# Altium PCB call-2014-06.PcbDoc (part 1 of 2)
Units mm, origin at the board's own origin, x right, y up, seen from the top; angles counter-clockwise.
Board outline 60 x 92 mm, 2 copper layers (Top Layer, Bottom Layer); 65 components, 45 nets, 265 pads, 33 vias.
Unrouted connection lines stored in the file: 4.
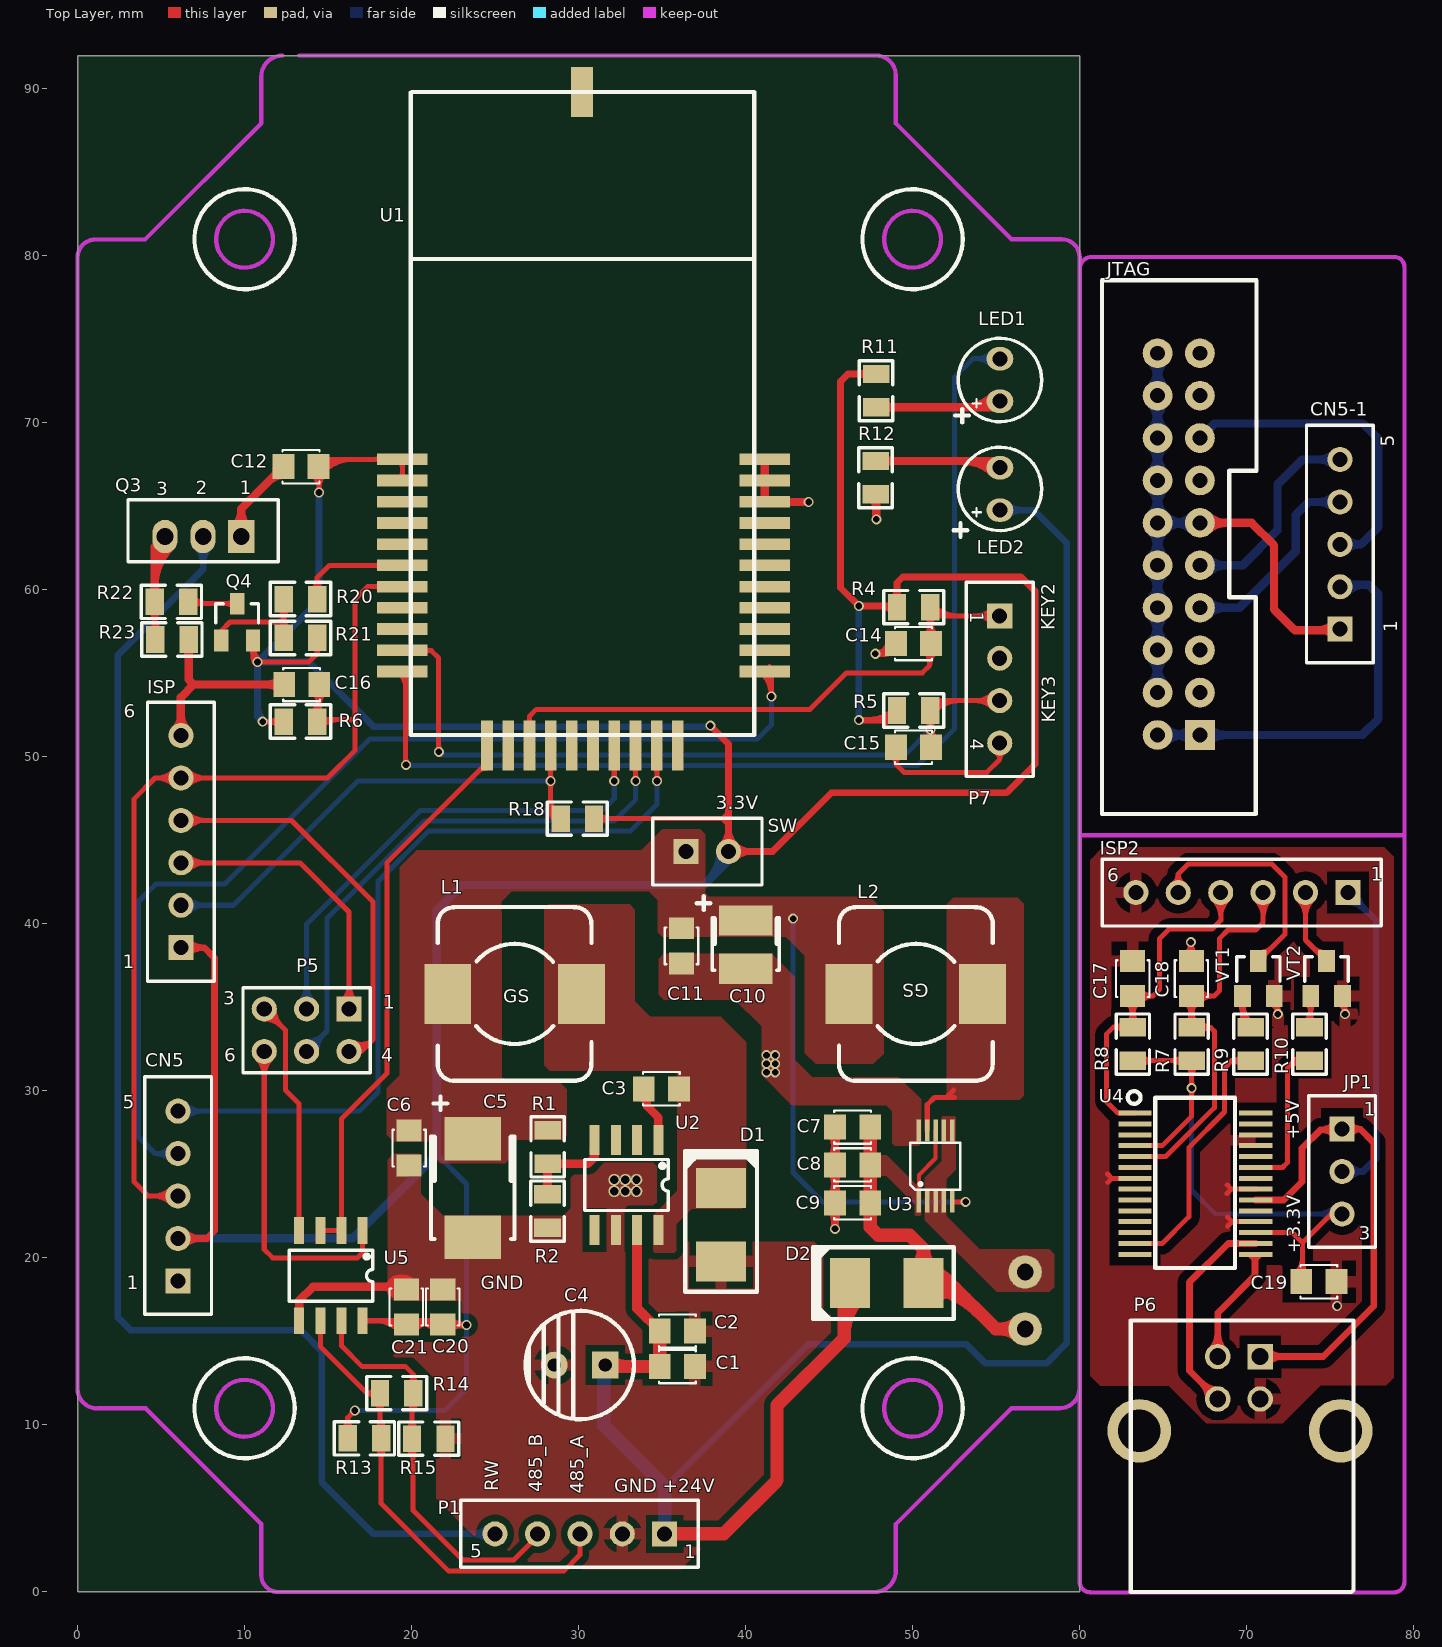
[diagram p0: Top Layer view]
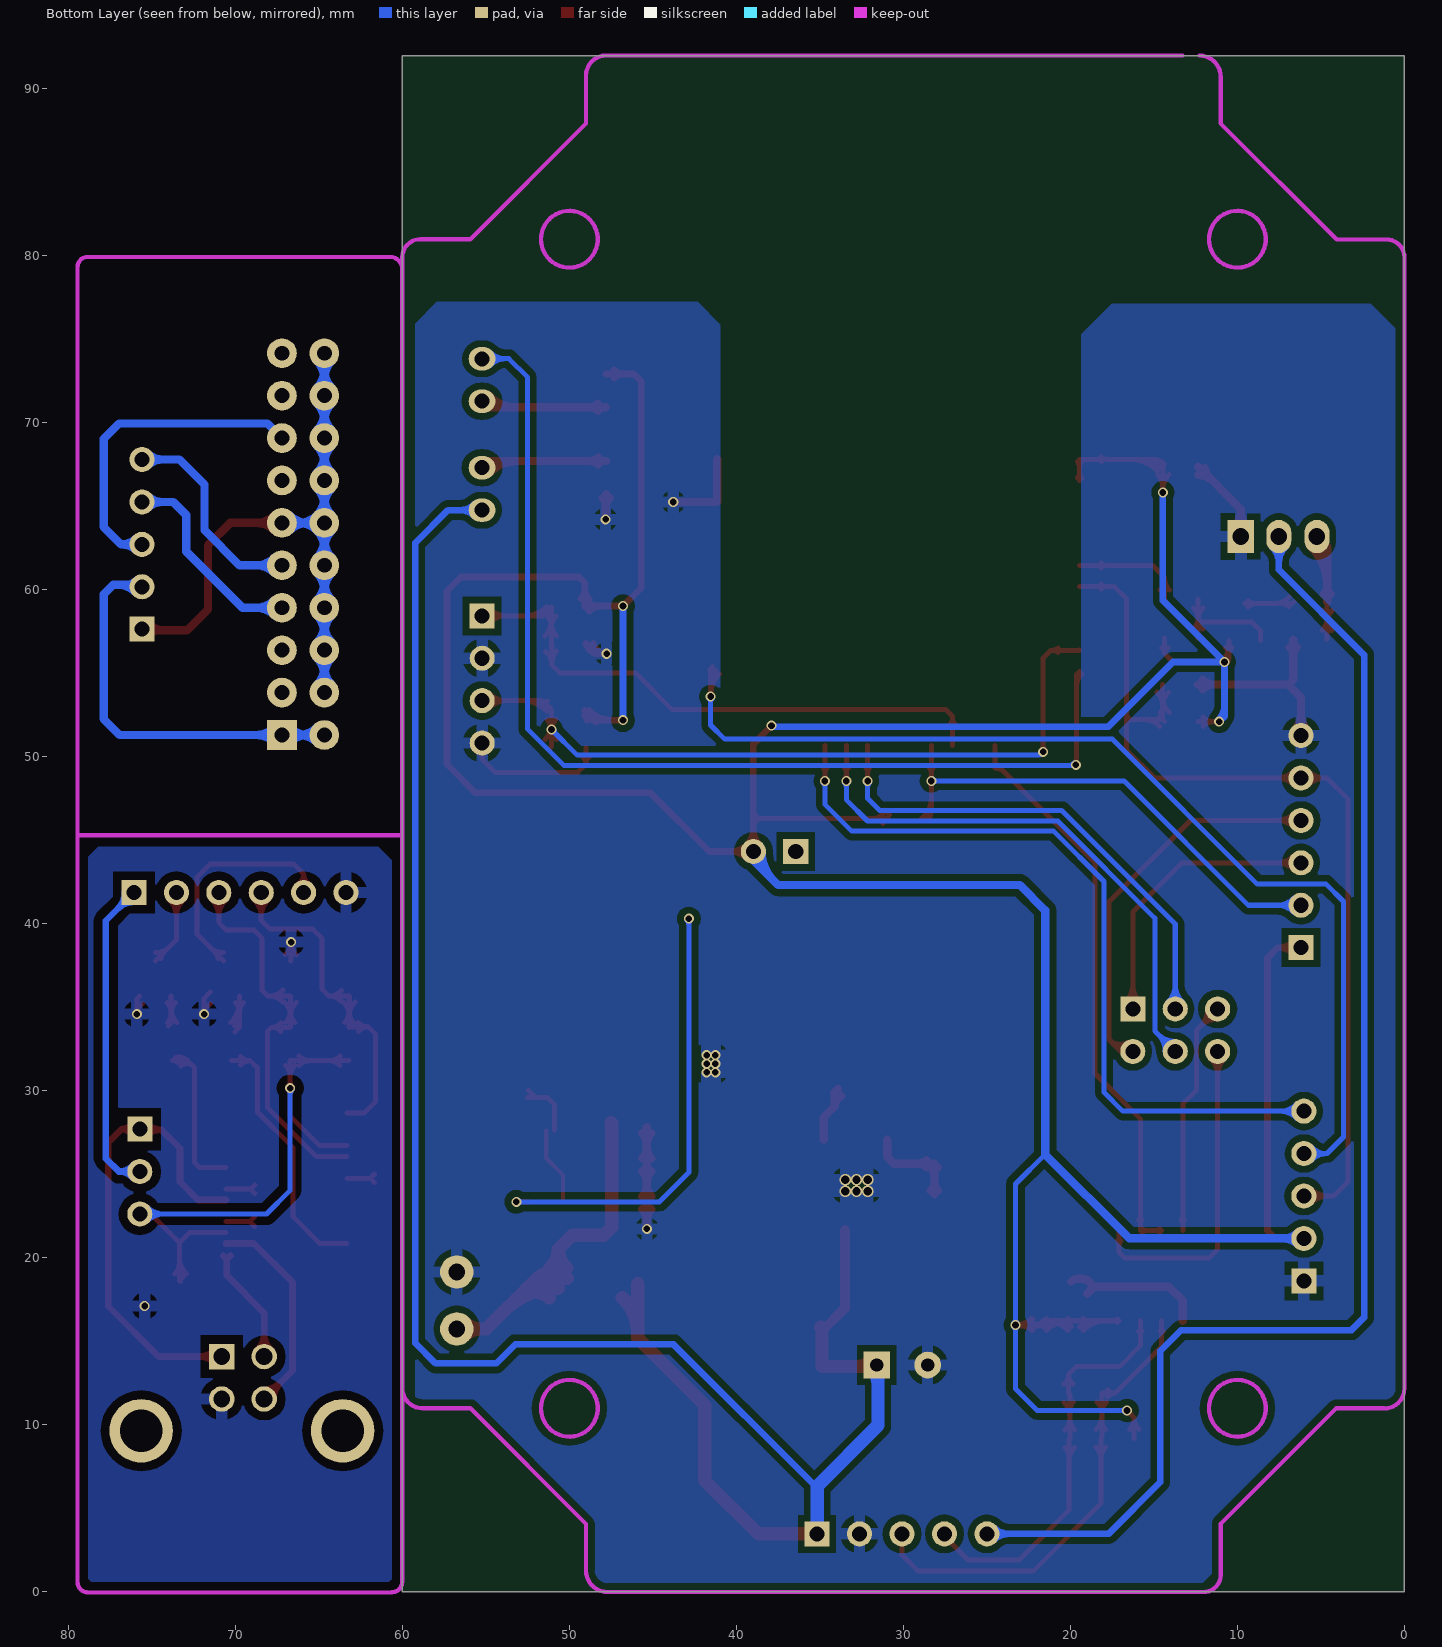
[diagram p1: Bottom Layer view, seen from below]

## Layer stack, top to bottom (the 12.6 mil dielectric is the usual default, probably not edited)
Top Layer: signal copper 0.0356
Dielectric: dielectric 0.32, FR-4, Dk 4.8
Bottom Layer: signal copper 0.0356

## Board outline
0,0 60,0 60,92 0,92

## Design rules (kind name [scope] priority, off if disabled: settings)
Clearance [All] p1: gap=0.2
ComponentClearance [All] p1: gap=0.254 collisioncheckmode=3 verticalgap=0.254
PolygonConnect [All] p1: connectstyle=Relief reliefconductorwidth=0.7 reliefentries=4 polygonreliefangle="90 Angle"
RoutingVias [All] p1: holewidth=0.711 width=1.27 viastyle="Through Hole" minholewidth=0.711 minwidth=1.27 maxholewidth=0.711 maxwidth=1.27
SolderMaskExpansion [All] p1: expansion=0.102
TestPointUsage [All] p1: valid=0 allowmultiple=FALSE
Testpoint [All] p1: side=15 testpointundercomponent=TRUE minsize=1.016 maxsize=2.54 preferedsize=1.524 minholesize=0 maxholesize=1.016 preferedholesize=0.813 testpointgrid=0.025 style=1023 order=0-112345678
Width [All] p1: maxlimit=2 minlimit=0.2 preferedwidth=0.254 toplayer_prefwidth=0.3 bottomlayer_prefwidth=0.3 minimp=50.000000 maximp=50.000000 favimp=50.000000
18 further rules are at their usual default settings.

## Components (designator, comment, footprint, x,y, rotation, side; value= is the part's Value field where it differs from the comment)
C1 "4.7μF/10%/0805" C-0805 37.62,14.4 r180 top
C2 "4.7μF/10%/0805" C-0805 37.62,16.52 r180 top
C3 "0.01μF/10%/0805" C-0805 33.26,29.23 r0 top
C4 "220μF" CZ3.0/6.5 30.07,13.59 r0 top
C5 "476C" C-TAN-D 21.17,28.43 r270 top
C6 "0.1μf/10%/0805" C-0805 20.75,24.88 r90 top
C7 "4.7μF/10%/0805" C-0805 44.71,26.94 r0 top
C8 "4.7μF/10%/0805" C-0805 44.71,24.67 r0 top
C9 "4.7μF/10%/0805" C-0805 44.71,22.4 r0 top
C10 "47uF/20%/10V/B" C-TAN-B 38.015,41.118 r270 top
C11 "0.1μf/10%/0805" C-0805 37.065,36.988 r90 top
C12 "0.1uf/10%/0805" C-0805 11.684,66.481 r0 top
C14 "0.1uf/10%/0805" C-0805 48.36,55.89 r0 top
C15 "0.1uf/10%/0805" C-0805 48.36,49.68 r0 top
C16 "0.1uf/10%/0805" C-0805 11.72,53.436 r0 top
C17 "100pf/10%/0805" C-0805 62.28,38.43 r270 top
C18 "100pf/10%/0805" C-0805 65.797,38.43 r270 top
C19 "0.1μf/10%/0805" C-0805 76.03,19.48 r180 top
C20 "0.1uf/10%/0805" C-0805 20.97,18.76 r270 top
C21 "1uf/10%/0805" C-0805 18.79,18.76 r270 top
CN5 "1*5/排针" PIN-S-2.54-1*5 6.02,18.63 r90 top
CN5-1 "1*5/排针座" PIN-S-2.54-1*5 75.59,57.65 r90 top
D1 "SMB" SMB 40.63,18.48 r90 top
D2 "1N5408/SMB" smb 51.96,20.59 r180 top
ISP "1*6/排针" PIN-S-2.54-1*6 6.19,38.58 r90 top
ISP2 "1*6/排针座" PIN-S-2.54-1*6 76.07,41.88 r180 top locked
JP1 "1*3/排针" PIN-S-2.54-1*3 75.72,27.71 r270 top
JTAG "2*10/排针" IDC-20 67.21,51.29 r90 top
L1 "15μH" GSDS104C2 26.17,35.81 r270 top
L2 "15μH" GSDS104C2 50.196,35.81 r270 top
LED1 "green LED" LED-φ3 55.23,72.57 r90 top
LED2 "VDD33" LED-φ3 55.23,66.05 r90 top
P1 "1*5/2.5" PIN-S-2.54-1*5 35.16,3.48 r180 top locked
P5 "2*3/排针" HDR2X3_CEN 16.26,34.91 r180 top
P6 "Header1*4" USB_B_90D 70.84,14.12 r270 top locked
P7 "1*4/2.54排针" PIN-S-2.54-1*4 55.22,58.45 r270 top (schematic designator P6)
Q3 "D882/TO-126" TO-126 7.52,63.199 r180 top
Q4 "MMBT3906LT1G/SOT-23" SOT-23 8.23,56.34 r0 top
R1 "10K" R-0805 29.05,25.15 r90 top
R2 "5.9K/1%/0805" R-0805 27.24,24.31 r270 top
R4 "10K/5%/0805" R-0805 51.57,59.87 r180 top
R5 "10K/5%/0805" R-0805 51.57,53.68 r180 top
R6 "10K/5%/0805" R-0805 14.851,53.016 r180 top
R7 "3.3K/5%/0805" R-0805 65.817,34.31 r270 top
R8 "3.3K/5%/0805" R-0805 62.29,34.31 r270 top
R9 "1K/5%/0805" R-0805 69.343,34.31 r270 top
R10 "1K/5%/0805" R-0805 72.87,34.31 r270 top
R11 "3.3K/5%/0805" R-0805 46.92,73.43 r270 top
R12 "1.5K/5%/0805" R-0805 48.69,65.22 r90 top
R13 "3.3K/5%/0805" R-0805 18.68,10.1 r180 top
R14 "120ohm" R-0805 20.61,12.8 r180 top
R15 "3.3K/5%/0805" R-0805 22.53,10.08 r180 top
R18 "10K/5%/0805" R-0805 28.425,45.404 r0 top
R20 "1K/5%/0805" R-0805 11.851,58.55 r0 top
R21 "10K/5%/0805" R-0805 11.851,56.23 r0 top
R22 "1K/5%/0805" R-0805 4.12,58.39 r0 top
R23 "10K/5%/0805" R-0805 7.15,57.93 r180 top
SW "SW-1" PIN-S-2.54-1*2 36.444,44.335 r0 top
U1 "STM32W_1" STM32W108-3 40.52,51.31 r90 top locked
U2 "TPS5430" SO-G8#1 32.86,24.37 r180 top locked
U3 "TPS62056" MSOP-10 50.38,23.46 r0 top locked
U4 "FT232R" SSOP-28 63.32,28.67 r0 top
U5 "MAX3485CSA" SO-G8#2 15.16,18.94 r180 top
VT1 "2N3904" SOT23-3 69.753,35.68 r0 top
VT2 "2N3904" SOT23-3 73.84,35.68 r0 top

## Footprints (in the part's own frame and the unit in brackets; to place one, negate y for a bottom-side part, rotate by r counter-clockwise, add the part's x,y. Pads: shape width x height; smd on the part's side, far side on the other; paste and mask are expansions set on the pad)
C-0805 [mm]
  rect 1.3x1.5 smd: 1(0.65,0.9) 2(2.75,0.9)
  silkscreen extent 0.6,-0.1 2.8,1.9
C-TAN-B [mm]
  rect 1.8x3.2 smd: 1(0.9,2) 2(3.8,2)
  silkscreen extent 0.75,0 3.9,4
C-TAN-D [mm]
  rect 2.6x3.4 smd: 1(1.3,2.5) 2(7.2,2.5)
  silkscreen extent 1.15,0 7.3,5
CZ3.0/6.5 [mm]
  rect 1.6x1.6 hole 0.8: 1(1.524,0)
  round 1.6 hole 0.8: 2(-1.524,0)
  silkscreen extent -3.25,-3.25 3.25,3.25
GSDS104C2 [mm]
  rect 3.6x2.8 smd: 1(0,4) 2(0,-4)
  silkscreen extent -5.2,-4.6 5.21,4.6
HDR2X3_CEN [mm] "Connector; Header; 3x2 Position"
  rect 1.5x1.5 hole 0.9: 1(0,0)
  round 1.5 hole 0.9: 2(2.54,0) 3(5.08,0) 4(0,2.54) 5(2.54,2.54) 6(5.08,2.54)
  silkscreen extent -1.27,-1.27 6.35,3.81
IDC-20 [mil]
  rect 70x70 hole 35: 1(1,0)
  round 70 hole 35: 2(1,100) 3(101,0) 4(101,100) 5(201,0) 6(201,100) 7(301,0) 8(301,100) 9(401,0) 10(401,100) 11(501,0) 12(501,100) 13(601,0) 14(601,100) 15(701,0) 16(701,100) 17(801,0) 18(801,100) 19(901,0) 20(901,100)
  silkscreen extent -185,-133 1073,231
LED-φ3 [mm]
  oval 1.4x1.6 hole 0.9: 1(-1.27,0) 2(1.27,0)
  silkscreen extent -2.5,-2.5 2.5,2.5
MSOP-10 [mm]
  rect 0.27x1.3 smd mask+0.05: 1(0,-0.1) 2(0.5,-0.1) 3(1,-0.1) 4(1.5,-0.1) 5(2,-0.1) 6(2,4.175) 7(1.5,4.175) 8(1,4.175) 9(0.5,4.175) 10(0,4.175)
  silkscreen extent -0.51,0.64 2.46,3.43
PIN-S-2.54-1*2 [mm]
  rect 1.5x1.5 hole 0.9: 1(0,0)
  round 1.5 hole 0.9: 2(2.54,0)
  silkscreen extent -2,-2 4.54,2
PIN-S-2.54-1*3 [mm]
  rect 1.5x1.5 hole 0.9: 1(0,0)
  round 1.5 hole 0.9: 2(2.54,0) 3(5.08,0)
  silkscreen extent -2,-2 7.08,2
PIN-S-2.54-1*4 [mm]
  rect 1.5x1.5 hole 0.9: 1(0,0)
  round 1.5 hole 0.9: 2(2.54,0) 3(5.08,0) 4(7.62,0)
  silkscreen extent -2,-2 9.62,2
PIN-S-2.54-1*5 [mm]
  rect 1.5x1.5 hole 0.9: 1(0,0)
  round 1.5 hole 0.9: 2(2.54,0) 3(5.08,0) 4(7.62,0) 5(10.16,0)
  silkscreen extent -2,-2 12.22,2
PIN-S-2.54-1*6 [mm]
  rect 1.5x1.5 hole 0.9: 1(0,0)
  round 1.5 hole 0.9: 2(2.54,0) 3(5.08,0) 4(7.62,0) 5(10.16,0) 6(12.7,0)
  silkscreen extent -2,-2 14.7,2
R-0805 [mm]
  rect 1.1x1.6 smd: 1(0.5,0.9) 2(2.5,0.9)
  silkscreen extent -0.3,-0.1 3.3,1.9
SMB [mm]
  rect 2.4x3 smd: 1(1.3,2.1) 2(5.7,2.1)
  silkscreen extent -0.51,-0.05 7.92,4.24
smb [mm]
  rect 2.4x3 smd: 1(1.3,2.1) 2(5.7,2.1)
  silkscreen extent -0.51,-0.05 7.92,4.24
SO-G8#1 [mm]
  rect 0.6x1.8 smd: 1(-1.916,-2.7) 2(-0.646,-2.7) 3(0.624,-2.7) 4(1.894,-2.7) 5(1.894,2.7) 6(0.624,2.7) 7(-0.646,2.7) 8(-1.916,2.7)
  silkscreen extent -2.51,-1.52 2.49,1.52
SO-G8#2 [mm]
  rect 0.6x1.6 smd: 1(-1.916,-2.7) 2(-0.646,-2.7) 3(0.624,-2.7) 4(1.894,-2.7) 5(1.894,2.7) 6(0.624,2.7) 7(-0.646,2.7) 8(-1.916,2.7)
  silkscreen extent -2.51,-1.52 2.49,1.52
SOT23-3 [mm]
  rect 1x1.3 smd: 1(0,0) 2(1.9,0) 3(0.95,2.1)
  silkscreen extent -0.35,0.87 2.25,2.35
SOT-23 [mm]
  rect 0.85x1.3 smd: 1(0.381,0.635) 2(2.281,0.635) 3(1.331,2.835)
  silkscreen extent 0.06,1.68 2.61,2.83
SSOP-28 [mm]
  rect 2x0.3 smd: 1(0,0) 2(0,-0.65) 3(0,-1.3) 4(0,-1.95) 5(0,-2.6) 6(0,-3.25) 7(0,-3.9) 8(0,-4.55) 9(0,-5.2) 10(0,-5.85) 11(0,-6.5) 12(0,-7.15) 13(0,-7.8) 14(0,-8.45) 15(7.239,-8.45) 16(7.239,-7.8) 17(7.239,-7.15) 18(7.239,-6.5) 19(7.239,-5.85) 20(7.239,-5.2) 21(7.239,-4.55) 22(7.239,-3.9) 23(7.239,-3.25) 24(7.239,-2.6) 25(7.239,-1.95) 26(7.239,-1.3) 27(7.239,-0.65) 28(7.239,0)
  silkscreen extent -0.43,-9.27 5.99,1.32
STM32W108-3 [mm]
  rect 0.7x3 smd: 1(16.51,21.074) 2(15.24,21.074) 3(13.97,21.074) 4(12.7,21.074) 5(11.43,21.074) 6(10.16,21.074) 7(8.89,21.074) 8(7.62,21.074) 9(6.35,21.074) 10(5.08,21.074) 11(3.81,21.074) 22(3.81,-0.627) 23(5.08,-0.627) 24(6.35,-0.627) 25(7.62,-0.627) 26(8.89,-0.627) 27(10.16,-0.627) 28(11.43,-0.627) 29(12.7,-0.627) 30(13.97,-0.627) 31(15.24,-0.627) 32(16.51,-0.627)
  rect 3x0.7 smd: 12(-0.627,16.002) 13(-0.627,14.732) 14(-0.627,13.462) 15(-0.627,12.192) 16(-0.627,10.922) 17(-0.627,9.652) 18(-0.627,8.382) 19(-0.627,7.112) 20(-0.627,5.842) 21(-0.627,4.572)
  rect 3x1.3 smd: ""(38.5,10.314)
  silkscreen extent 0,0 38.5,20.57
TO-126 [mm]
  rect 1.6x2 hole 1: 1(-2.28,0)
  oval 1.5x2 hole 1: 2(0,0) 3(2.28,0)
  silkscreen extent -4.5,-2.2 4.5,1.5
USB_B_90D [mil] "180度 横插 方口USB母座"
  rect 60.06x60.06 hole 40: 1(1,-1)
  round 60.06 hole 40: 2(1,-101) 3(101,-101) 4(101,-1)
  round 150 hole 100: 5(176,-286) 6(176,189)
  silkscreen extent -84,-306 556,219

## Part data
C1 C2 C3 C6 C7 C8 C9 C11 C12 C14 C15 C16 C17 C18 C19 C20 C21: library part Cap, "Capacitor"
C4 C5: library part "Cap Pol1", "Polarized Capacitor (Radial)"
C10: library part ASC-0013BA
CN5 CN5-1: library part Header1*5
D1 D2: library part "Diode 1N5408", "3 Amp Medium Power Silicon Rectifier Diode"
ISP ISP2: library part Header1*6
JP1: library part Header1*3
JTAG: library part Header2*10
L1 L2: library part Inductor, "Inductor"
LED1: library part LED
LED2: library part LED3, "Typical BLUE SiC LED"
P1 P6 P7: library part "Header 4", "Header, 4-Pin"
P5: library part "Header 3X2A", "Header, 3-Pin, Dual row"
Q3: library part NPN-1E2C3B
Q4: library part ASQ-0009BA
R1 R2 R4 R5 R6 R12 R18: library part Res2, "Resistor"
R7 R8: library part RES_1
R9 R10 R11 R13 R14 R15 R20 R21 R22 R23: library part RES, "R"
U1: library part STM32W108-3
U5: library part MAX485CSA, "Low-Power, Slew-Rate-Limited RS-485/RS-422 Transceiver"
VT1 VT2: library part NPN, "NPN Transistor"

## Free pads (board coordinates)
  round 0.7 hole 0.5: 0(32.137,23.996) 0(32.137,24.683) 1(32.804,23.996) 1(32.804,24.683) 2(33.472,23.996) 2(33.472,24.683)
  round 2 hole 1: 0(56.74,15.75) 1(56.74,19.16)

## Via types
v1: diameter 0.6, hole 0.4, Top Layer to Bottom Layer, 33 vias

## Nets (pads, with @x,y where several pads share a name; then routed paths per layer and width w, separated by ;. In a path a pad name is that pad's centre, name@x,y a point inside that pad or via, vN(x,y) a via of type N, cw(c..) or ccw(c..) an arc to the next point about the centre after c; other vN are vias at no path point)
485_A: P1.3 R13.1 R14.2 U5.6 | length 34.3
  Top Layer w0.3: U5.6@14.43,15.634 cw(c14.174,15.378) 14.536,15.378 cw(c14.898,15.378) U5.6@14.642,15.634 ; U5.6@14.536,16.24 14.536,14.694 17.33,11.9 ; R14.2@17.785,11.667 ccw(c17.33,11.34) 17.33,11.9 ; R14.2@17.785,12.133 cw(c17.33,12.46) 17.33,11.9 ; R14.2@17.827,11.367 cw(c17.144,10.684) 18.11,10.684 cw(c19.076,10.684) R14.2@18.393,11.367 ; R13.1@17.897,8.667 cw(c17.214,7.984) 18.18,7.984 cw(c19.146,7.984) R13.1@18.463,8.667 ; R13.1@17.897,9.733 ccw(c17.383,10.247) 18.11,10.247 ; 18.11,10.585 ccw(c19.315,10.585) R13.1@18.463,9.733 ; P1.3@30.08,3.48 30.08,2.21 29.116,1.246 22.23,1.246 18.18,5.296 R13.1@18.18,9.2 18.11,9.27 R14.2@18.11,11.9 17.33,11.9
485_B: P1.4 R14.1 R15.2 U5.7 | length 30.6
  Top Layer w0.3: U5.7@15.7,15.634 cw(c15.444,15.378) 15.806,15.378 cw(c16.168,15.378) U5.7@15.912,15.634 ; U5.7@15.806,16.24 15.806,14.734 17.05,13.49 19.65,13.49 20.11,13.03 ; R15.2@19.747,8.647 cw(c18.919,7.819) 20.09,7.819 ; R15.2@19.747,9.713 ccw(c19.064,10.396) 20.03,10.396 ccw(c20.996,10.396) R15.2@20.313,9.713 ; R14.1@19.827,11.367 cw(c19.337,10.877) 20.03,10.877 ; R14.1@19.847,12.451 ccw(c19.342,13.03) 20.11,13.03 ; 20.03,10.491 cw(c21.269,10.491) R14.1@20.393,11.367 ; 20.09,8.109 cw(c20.851,8.109) R15.2@20.313,8.647 ; R14.1@20.373,12.451 cw(c20.878,13.03) 20.11,13.03 ; P1.4@27.54,3.48 27.54,3.328 26.125,1.913 23.07,1.913 20.09,4.893 20.09,9.12 R15.2@20.03,9.18 20.03,11.82 R14.1@20.11,11.9 20.11,13.03
+VBRD: CN5-1.2 JTAG.1 JTAG.2 | length 32.8
  Bottom Layer w0.5: JTAG.2@64.67,51.315 76.925,51.315 77.89,52.28 77.89,59.74 77.31,60.32 75.72,60.32 CN5-1.2@75.59,60.19 ; JTAG.2@65.122,50.864 cw(c66.213,49.773) 66.213,51.315 cw(c66.213,52.858) JTAG.2@65.122,51.767 ; JTAG.1@66.758,50.864 ccw(c65.667,49.773) 65.667,51.315 ccw(c65.667,52.858) JTAG.1@66.758,51.767 ; JTAG.1@67.662,50.864 cw(c68.753,49.773) 68.753,51.315 cw(c68.753,52.858) JTAG.1@67.662,51.767 ; CN5-1.2@75.944,59.836 cw(c77.111,58.669) 77.111,60.32 ; CN5-1.2@75.944,60.544 ccw(c76.483,61.083) 76.483,60.32
/RESET: C16.2 CN5-1.3 CN5.3 ISP2.5 ISP.5 JTAG.15 R6.1 U1.7 VT1.3 | length 107.7
  Top Layer w0.3: CN5.3@5.596,23.286 ccw(c4.571,22.261) 4.571,23.71 ccw(c4.571,25.159) CN5.3@5.596,24.134 ; ISP.5@5.766,48.316 ccw(c4.741,47.291) 4.741,48.74 ccw(c4.741,50.189) ISP.5@5.766,49.164 ; CN5.3@6.02,23.71 4.23,23.71 3.39,24.55 3.39,47.49 4.64,48.74 14.967,48.74 16.628,50.401 16.628,59.461 17.367,60.2 U1.7@19.446,60.2 ; ISP.5@6.614,48.316 cw(c7.639,47.291) 7.639,48.74 cw(c7.639,50.189) ISP.5@6.614,49.164 ; R6.1@14.068,52.649 ccw(c13.098,53.619) C16.2@14.47,53.619 ; C16.2@14.116,53.882 cw(c13.263,53.029) 14.47,53.029 cw(c15.677,53.029) C16.2@14.824,53.882 ; R6.1@14.351,52.116 R6.1@14.47,52.235 ; 14.47,53.044 ccw(c15.029,53.044) R6.1@14.634,52.649 ; C16.2@14.47,54.336 R6.1@14.47,52.235 ; R6.1@14.634,51.833 cw(c15.604,50.863) 15.604,52.235 ; R6.1@14.634,52.399 ccw(c15.029,52.794) 15.029,52.235 ; 16.628,52.019 16.412,52.235 ; 16.628,52.451 16.412,52.235 ; U1.7@18.155,60.059 ccw(c17.813,59.717) 17.813,60.2 ccw(c17.813,60.683) U1.7@18.155,60.341 ; ISP2.5@65.581,42.382 ccw(c65.183,42.99) 65.91,42.99 ; ISP2.5@65.91,41.88 65.91,42.99 ; ISP2.5@66.239,42.382 cw(c66.637,42.99) 65.91,42.99 ; VT1.3@70.703,37.78 72.29,39.367 72.29,42.81 71.51,43.59 66.51,43.59 65.91,42.99 ; VT1.3@70.703,38.28 ccw(c70.703,39.487) 71.556,38.634 ; VT1.3@71.053,37.93 cw(c71.536,37.93) VT1.3@71.194,38.271 ; R6.1@14.47,52.235 16.412,52.235
  Bottom Layer w0.5: JTAG.15@67.21,69.095 68.085,69.97 76.96,69.97 77.89,69.04 77.89,63.78 76.84,62.73 CN5-1.3@75.59,62.73 ; CN5-1.3@75.944,62.376 cw(c76.797,61.523) 76.797,62.73 cw(c76.797,63.937) CN5-1.3@75.944,63.084
BOOT: ISP2.2 ISP.2 R18.1 U1.15 VT2.3 | length 44.7
  Top Layer w0.3: U1.15@28.187,49.392 cw(c27.845,49.05) 28.328,49.05 cw(c28.811,49.05) U1.15@28.469,49.392 ; v1@28.222,48.453 cw(c27.966,48.197) 28.328,48.197 cw(c28.69,48.197) v1@28.434,48.453 ; v1@28.222,48.665 ccw(c27.966,48.921) 28.328,48.921 ccw(c28.69,48.921) v1@28.434,48.665 ; 28.328,46.788 ccw(c29.159,46.788) R18.1@28.571,46.2 ; 28.328,47.512 ccw(c29.883,47.512) R18.1@28.784,46.413 ; U1.15@28.328,50.683 28.328,46.901 R18.1@28.925,46.304 ; ISP2.2@73.106,41.456 cw(c72.081,40.431) 73.53,40.431 cw(c74.979,40.431) ISP2.2@73.954,41.456 ; ISP2.2@73.53,41.88 73.53,39.04 VT2.3@74.79,37.78 ; 73.936,38.634 ccw(c74.79,39.487) VT2.3@74.79,38.28 ; VT2.3@74.299,38.271 cw(c73.957,37.93) VT2.3@74.44,37.93
  Bottom Layer w0.3: ISP.2@6.19,41.12 9.342,41.12 16.781,48.559 v1(28.328,48.559) ; ISP.2@6.614,40.696 cw(c7.639,39.671) 7.639,41.12 cw(c7.639,42.569) ISP.2@6.614,41.544 ; v1@28.222,48.453 ccw(c27.966,48.197) 27.966,48.559 ccw(c27.966,48.921) v1@28.222,48.665
CBUS0: R10.2 U4.23 | length 13.5
  Top Layer w0.3: U4.23@70.559,25.42 72.15,25.42 72.44,25.71 72.44,31.4 72.85,31.81 ; 72.476,31.436 cw(c73.228,30.684) R10.2@73.495,31.713 ; 72.515,31.475 cw(c72.904,31.086) R10.2@73.261,31.505 ; 72.745,31.705 cw(c73.116,31.334) R10.2@73.455,31.734 ; 72.847,31.807 cw(c73.381,31.273) R10.2@73.57,32.004 ; R10.2@73.168,31.62 ccw(c72.85,31.449) 72.85,31.81 ; R10.2@73.168,32 cw(c72.85,32.171) 72.85,31.81 ; R10.2@73.77,31.81 72.85,31.81
CBUS2: R9.2 U4.13 | length 16.7
  Top Layer w0.3: U4.13@63.32,20.87 64.95,20.87 66.54,22.46 66.54,26.606 68.678,28.744 68.678,31.378 69.11,31.81 ; R9.2@69.693,31.546 ccw(c69.11,31.035) 69.11,31.81 ; R9.2@69.693,32.074 cw(c69.11,32.585) 69.11,31.81 ; R9.2@70.243,31.81 69.11,31.81
D+: P6.2 U4.15 | length 9.5
  Top Layer w0.4: P6.2@67.877,14.492 ccw(c66.916,15.453) 68.275,15.453 ccw(c69.633,15.453) P6.2@68.672,14.492 ; P6.2@68.275,14.095 68.275,16.715 70.51,18.95 70.51,19.92 ; U4.15@70.29,20.14 70.51,19.92 ; U4.15@70.73,20.14 70.51,19.92
D-: P6.3 U4.16 | length 14.8
  Top Layer w0.4: P6.3@67.712,11.555 ccw(c66.353,11.555) 67.314,12.515 ccw(c68.275,13.476) P6.3@68.275,12.117 ; P6.3@68.275,11.555 66.58,13.249 66.58,18.55 68.9,20.87 U4.16@70.559,20.87
GND: C1.1 C2.1 C4.2 C5.2 C6.1 C7.1 C8.1 C9.1 C10.2 C11.1 C12.1 C14.1 C15.1 C16.1 C17.1 C18.1 C19.1 C20.1 C21.1 CN5.1 D1.1 ISP2.6 ISP.6 P1.2 P6.4 P7.2 P7.4 pad.0@32.137,23.996 pad.0@32.137,24.683 pad.1 pad.2 Q3.1 R2.2 R12.1 R15.1 R23.1 U1.30 U1.31 U1.32 U2.6 U3.2 U3.3 U3.4 U3.6 U3.7 U3.10 U4.7 U4.18 U4.21 U4.25 U4.26 U5.5 VT1.2 VT2.2 | length 85.6
  Top Layer w0.3: C15.1@48.74,50.059 cw(c48.421,49.564) 49.01,49.564 ; C15.1@49.01,50.58 49.01,49.564 ; C15.1@49.28,50.059 ccw(c49.599,49.564) 49.01,49.564 ; P7.4@54.947,50.296 cw(c54.72,49.85) 55.22,49.85 ; P7.4@55.22,50.83 55.22,49.85 ; P7.4@55.493,50.296 ccw(c55.72,49.85) 55.22,49.85 ; 61.67,24.51 61.93,24.77 ; 61.67,25.03 61.93,24.77 ; U4.7@63.32,24.77 61.93,24.77 ; C18.1@66.344,38.134 ccw(c65.58,38.897) v1@66.66,38.897 ; v1@66.554,38.804 cw(c66.298,38.548) 66.66,38.548 cw(c67.022,38.548) v1@66.766,38.804 ; C18.1@66.697,37.78 66.66,37.817 v1(66.66,38.91) ccw(c67.617,38.91) C18.1@67.013,38.168 ; 68.83,23.86 69.09,24.12 ; 68.83,24.38 69.09,24.12 ; 68.85,21.88 69.14,22.17 ; 68.85,22.46 69.14,22.17 ; U4.18@70.559,22.17 69.14,22.17 ; U4.21@70.559,24.12 69.09,24.12 ; VT1.2@71.485,35.223 cw(c71.132,34.575) v1@71.87,34.575 ; VT1.2@71.5,35.92 71.87,35.55 v1(71.87,34.6) ; v1@71.764,34.706 ccw(c71.508,34.962) 71.87,34.962 ccw(c72.232,34.962) v1@71.976,34.706 ; VT2.2@75.548,35.237 cw(c75.122,34.586) v1@75.9,34.586 ; VT2.2@75.74,35.68 75.9,35.52 v1(75.9,34.6) ; v1@75.794,34.706 ccw(c75.538,34.962) 75.9,34.962 ccw(c76.262,34.962) v1@76.006,34.706 ; 49.01,49.564 49.492,49.082 54.452,49.082 55.22,49.85
  Top Layer w0.4: 48.286,56.179 ccw(c48.286,56.876) C14.1@48.962,56.702 ; C14.1@48.574,56.802 cw(c47.77,57.009) v1(47.77,56.179) 48.399,56.179 C14.1@49.01,56.79
  Top Layer w0.5: ISP.6@5.836,51.634 ccw(c4.983,52.487) 6.19,52.487 ccw(c7.397,52.487) ISP.6@6.544,51.634 ; ISP.6@6.19,51.28 6.19,53.571 6.955,54.336 ; R23.1@6.438,56.568 cw(c5.926,56.056) 6.65,56.056 cw(c7.374,56.056) R23.1@6.862,56.568 ; R23.1@6.65,57.03 6.65,54.641 6.955,54.336 ; Q3.1@9.411,63.788 ccw(c8.472,64.727) 9.8,64.727 ccw(c11.128,64.727) Q3.1@10.189,63.788 ; Q3.1@9.8,63.199 9.8,64.847 C12.1@12.334,67.381 ; 11.48,66.527 cw(c12.334,65.674) C12.1@12.334,66.881 ; C12.1@11.722,66.769 ccw(c11.21,67.281) C12.1@11.934,67.281 ; C16.1@12.087,54.053 ccw(c11.404,53.37) 11.404,54.336 ccw(c11.404,55.302) C16.1@12.087,54.619 ; C16.1@12.37,54.336 6.955,54.336 ; U5.5@13.266,16.24 13.266,17.446 14.094,18.274 18.57,18.274 C21.1@18.989,18.693 ; 18.588,18.275 C21.1@19.007,17.856 ; 18.802,18.506 cw(c19.425,17.884) C21.1@19.945,18.594 ; U1.32@41.147,67.833 U1.30@41.147,65.28 41.161,65.266 v1(43.779,65.266) ; C9.1@45.077,22.917 cw(c44.394,22.234) 45.36,22.234 cw(c46.326,22.234) C9.1@45.643,22.917 ; C9.1@45.077,23.683 ccw(c44.394,24.366) 45.36,24.366 ccw(c46.326,24.366) C9.1@45.643,23.683 ; C8.1@45.077,25.187 cw(c44.394,24.504) 45.36,24.504 cw(c46.326,24.504) C8.1@45.643,25.187 ; C8.1@45.077,25.953 ccw(c44.394,26.636) 45.36,26.636 ccw(c46.326,26.636) C8.1@45.643,25.953 ; C7.1@45.077,27.457 cw(c44.394,26.774) 45.36,26.774 cw(c46.326,26.774) C7.1@45.643,27.457 ; v1(45.36,21.742) C7.1@45.36,27.84 ; R12.1@47.578,65.508 cw(c46.976,64.906) 47.827,64.906 ; R12.1@47.79,65.72 47.827,65.683 v1(47.827,64.227) ; 47.827,65.085 cw(c48.425,65.085) R12.1@48.002,65.508
  other v1: 75.43,17.12 41.259,31.118 41.775,31.118 41.259,31.629 41.775,31.629 41.259,32.14 41.775,32.14
GND1: CN5-1.1 JTAG.4 JTAG.6 JTAG.8 JTAG.10 JTAG.11 JTAG.12 JTAG.14 JTAG.16 JTAG.18 JTAG.20 | length 84
  Top Layer w0.5: JTAG.11@67.21,64.015 70.305,64.015 71.64,62.68 71.64,58.84 72.9,57.58 75.52,57.58 CN5-1.1@75.59,57.65 ; JTAG.11@67.662,63.564 cw(c68.753,62.473) 68.753,64.015 cw(c68.753,65.558) JTAG.11@67.662,64.467 ; 74.214,57.58 ccw(c74.214,59.026) CN5-1.1@75.236,58.004 ; 74.552,57.58 cw(c74.552,56.612) CN5-1.1@75.236,57.296
  Bottom Layer w0.5: JTAG.4@64.218,54.307 ccw(c63.127,55.398) 64.67,55.398 ccw(c66.213,55.398) JTAG.4@65.122,54.307 ; JTAG.6@64.218,55.944 cw(c63.127,54.853) 64.67,54.853 cw(c66.213,54.853) JTAG.6@65.122,55.944 ; JTAG.6@64.218,56.847 ccw(c63.127,57.938) 64.67,57.938 ccw(c66.213,57.938) JTAG.6@65.122,56.847 ; JTAG.8@64.218,58.484 cw(c63.127,57.393) 64.67,57.393 cw(c66.213,57.393) JTAG.8@65.122,58.484 ; JTAG.8@64.218,59.387 ccw(c63.127,60.478) 64.67,60.478 ccw(c66.213,60.478) JTAG.8@65.122,59.387 ; JTAG.10@64.218,61.024 cw(c63.127,59.933) 64.67,59.933 cw(c66.213,59.933) JTAG.10@65.122,61.024 ; JTAG.10@64.218,61.927 ccw(c63.127,63.018) 64.67,63.018 ccw(c66.213,63.018) JTAG.10@65.122,61.927 ; JTAG.12@64.218,63.564 cw(c63.127,62.473) 64.67,62.473 cw(c66.213,62.473) 65.122,63.564 cw(c66.213,62.473) 66.213,64.015 cw(c66.213,65.558) 65.122,64.467 cw(c66.213,65.558) 64.67,65.558 cw(c63.127,65.558) JTAG.12@64.218,64.467 ; JTAG.14@64.218,66.104 cw(c63.127,65.013) 64.67,65.013 cw(c66.213,65.013) JTAG.14@65.122,66.104 ; JTAG.14@64.218,67.007 ccw(c63.127,68.098) 64.67,68.098 ccw(c66.213,68.098) JTAG.14@65.122,67.007 ; JTAG.16@64.218,68.644 cw(c63.127,67.553) 64.67,67.553 cw(c66.213,67.553) JTAG.16@65.122,68.644 ; JTAG.16@64.218,69.547 ccw(c63.127,70.638) 64.67,70.638 ccw(c66.213,70.638) JTAG.16@65.122,69.547 ; JTAG.18@64.218,71.184 cw(c63.127,70.093) 64.67,70.093 cw(c66.213,70.093) JTAG.18@65.122,71.184 ; JTAG.18@64.218,72.087 ccw(c63.127,73.178) 64.67,73.178 ccw(c66.213,73.178) JTAG.18@65.122,72.087 ; JTAG.20@64.218,73.724 cw(c63.127,72.633) 64.67,72.633 cw(c66.213,72.633) JTAG.20@65.122,73.724 ; JTAG.4@64.67,53.855 64.67,63.89 64.795,64.015 JTAG.11@67.21,64.015 ; JTAG.12@64.67,64.015 JTAG.20@64.67,74.175 ; JTAG.11@66.758,63.564 ccw(c65.667,62.473) 65.667,64.015 ccw(c65.667,65.558) JTAG.11@66.758,64.467
JNTRST: JTAG.3
JTCK: CN5-1.5 CN5.5 JTAG.9 U1.20 | length 68.3
  Top Layer w0.3: U1.20@34.537,49.392 cw(c34.144,48.999) 34.699,48.999 ; v1@34.593,48.665 ccw(c34.337,48.921) 34.699,48.921 ccw(c35.061,48.921) v1@34.805,48.665 ; U1.20@34.678,50.683 34.699,50.662 v1(34.699,48.559) ; 34.699,49.101 cw(c35.11,49.101) U1.20@34.819,49.392
  Bottom Layer w0.3: CN5.5@6.02,28.79 16.862,28.79 17.987,29.915 17.987,42.541 21.003,45.557 33.089,45.557 34.699,47.167 v1(34.699,48.559) ; CN5.5@6.444,28.366 cw(c7.469,27.341) 7.469,28.79 cw(c7.469,30.239) CN5.5@6.444,29.214 ; v1@34.593,48.453 cw(c34.337,48.197) 34.699,48.197 cw(c35.061,48.197) v1@34.805,48.453
  Bottom Layer w0.5: JTAG.9@67.21,61.475 69.745,61.475 71.85,63.58 71.85,66.31 73.35,67.81 CN5-1.5@75.59,67.81 ; JTAG.9@67.662,61.024 cw(c68.753,59.933) 68.753,61.475 cw(c68.753,63.018) JTAG.9@67.662,61.927 ; CN5-1.5@75.236,67.456 ccw(c74.383,66.603) 74.383,67.81 ccw(c74.383,69.017) CN5-1.5@75.236,68.164
JTDI: JTAG.5
JTDO: JTAG.13
JTMS: CN5-1.4 CN5.4 JTAG.7 U1.22 | length 85
  Top Layer w0.3: U1.22@41.006,54.979 cw(c39.708,53.681) v1@41.543,53.681 ; U1.22@41.218,55.191 cw(c40.432,54.405) 41.543,54.405 ; U1.22@41.43,55.403 cw(c41.157,55.13) U1.22@41.543,55.13 ; v1@41.437,53.722 ccw(c41.181,53.978) 41.543,53.978 ccw(c41.905,53.978) v1@41.649,53.722 ; v1(41.543,53.616) 41.543,55.159 U1.22@41.594,55.21
  Bottom Layer w0.3: CN5.4@5.582,25.84 ccw(c4.638,24.959) 4.638,26.25 ; CN5.4@5.582,26.66 cw(c4.638,27.541) 4.638,26.25 ; CN5.4@6.02,26.25 4.638,26.25 ; v1@41.437,53.51 cw(c41.181,53.254) 41.543,53.254 cw(c41.905,53.254) v1@41.649,53.51 ; v1(41.543,53.616) 41.543,51.912 40.692,51.061 17.481,51.061 8.804,42.384 4.683,42.384 3.649,41.35 3.649,27.239 4.638,26.25
  Bottom Layer w0.5: JTAG.7@67.21,58.935 69.575,58.935 72.94,62.3 72.94,64.49 73.72,65.27 CN5-1.4@75.59,65.27 ; JTAG.7@67.662,58.484 cw(c68.753,57.393) 68.753,58.935 cw(c68.753,60.478) JTAG.7@67.662,59.387 ; CN5-1.4@75.236,64.916 ccw(c74.383,64.063) 74.383,65.27 ccw(c74.383,66.477) CN5-1.4@75.236,65.624
KEY2: C14.2 P7.1 R4.1 U1.14 | length 45.8
  Top Layer w0.3: U1.14@26.917,51.974 ccw(c26.575,52.316) 27.058,52.316 ccw(c27.541,52.316) U1.14@27.199,51.974 ; U1.14@27.058,50.683 27.058,52.435 27.474,52.851 43.86,52.851 46.045,55.036 50.584,55.036 51.028,55.48 51.028,56.708 C14.2@51.11,56.79 ; C14.2@50.756,56.336 cw(c50.101,55.681) 51.028,55.681 ; C14.2@50.756,57.244 ccw(c49.999,58.001) 51.07,58.001 ; R4.1@50.787,58.437 cw(c50.104,57.754) 51.07,57.754 cw(c52.036,57.754) R4.1@51.353,58.437 ; 51.028,55.477 cw(c52.082,55.477) C14.2@51.423,56.3 ; C14.2@51.028,56.392 51.07,56.434 R4.1@51.07,58.97 51.59,58.45 P7.1@55.22,58.45 ; R4.1@51.07,58.194 ccw(c52.414,58.194) C14.2@51.464,57.244 ; R4.1@51.141,58.791 ccw(c51.963,59.613) 51.963,58.45 ; R4.1@51.353,59.003 ccw(c52.688,60.338) 52.688,58.45 ; P7.1@54.796,58.026 ccw(c53.771,57.001) 53.771,58.45 ccw(c53.771,59.899) P7.1@54.796,58.874
KEY3: C15.2 P7.3 R5.1 U1.10 | length 57
  Top Layer w0.3: U1.10@19.446,56.39 19.45,56.394 19.481,56.363 21.186,56.363 21.625,55.924 v1@21.625,50.306 ; U1.10@20.737,56.249 cw(c21.014,55.972) 21.014,56.363 ; U1.10@20.737,56.531 ccw(c21.144,56.938) 21.144,56.363 ; v1@21.526,50.412 ccw(c21.287,50.651) 21.625,50.651 ; 21.625,50.685 ccw(c22.011,50.685) v1@21.738,50.412 ; C15.2@50.756,51.034 ccw(c49.999,51.791) v1@51.07,51.791 ; R5.1@50.787,52.247 cw(c50.104,51.564) 51.07,51.564 cw(c52.036,51.564) R5.1@51.353,52.247 ; v1@50.964,51.541 cw(c50.708,51.285) 51.07,51.285 cw(c51.432,51.285) v1@51.176,51.541 ; v1@50.964,51.753 ccw(c50.708,52.009) 51.07,52.009 ccw(c51.432,52.009) v1@51.176,51.753 ; R5.1@51.07,51.984 ccw(c52.414,51.984) C15.2@51.464,51.034 ; C15.2@51.137,50.553 51.07,50.62 R5.1@51.07,52.78 51.66,53.37 ; R5.1@51.141,52.959 cw(c52.132,51.968) 52.132,53.37 ; R5.1@51.314,53.347 ccw(c51.474,53.556) 51.66,53.37 ; R5.1@51.353,52.747 cw(c52.857,51.243) 52.857,53.37 ; R5.1@51.47,53.03 cw(c51.832,53.03) R5.1@51.576,53.286 ; P7.3@54.796,52.946 ccw(c53.771,51.921) 53.771,53.37 ccw(c53.771,54.819) P7.3@54.796,53.794 ; P7.3@55.22,53.37 51.66,53.37
  Bottom Layer w0.3: v1(21.632,50.306) 21.836,50.102 49.525,50.102 v1(51.07,51.647) ; v1@50.92,51.647 cw(c50.558,51.647) 50.814,51.391 cw(c51.07,51.135) v1@51.07,51.497
NetC3_1: C3.1 U2.1 | length 4.2
  Top Layer w0.5: C3.1@33.73,29.673 cw(c33.426,29.071) 34.1,29.071 ; C3.1@33.91,30.13 34.1,29.94 34.1,29.09 34.776,28.414 U2.1@34.776,27.07
NetC3_2: C3.2 D1.2 L1.1 U2.8
NetC5_1: C5.1 C6.2 C10.1 C11.2 L1.2 L2.2 R1.2 SW.1 U3.5 | length 28.7
  Top Layer w0.3: U3.5@52.417,23.359 v1(53.176,23.359) ; v1@53.07,23.253 ccw(c52.814,22.997) 52.814,23.359 ccw(c52.814,23.721) v1@53.07,23.465
  Bottom Layer w0.3: v1@42.741,40.207 cw(c42.485,39.951) 42.847,39.951 cw(c43.209,39.951) v1@42.953,40.207 ; v1(42.847,40.313) 42.847,25.117 44.605,23.359 v1(53.176,23.359) ; v1@53.07,23.253 ccw(c52.814,22.997) 52.814,23.359 ccw(c52.814,23.721) v1@53.07,23.465
NetISP2_1: ISP2.1 JP1.2 | length 23
  Bottom Layer w0.4: JP1.2@75.72,25.17 76.97,25.17 ; ISP2.1@76.07,41.33 cw(c76.07,40.002) 77.009,40.941 cw(c77.948,41.88) ISP2.1@76.62,41.88 ; ISP2.1@76.07,41.88 77.76,40.19 77.76,25.96 76.97,25.17 ; JP1.2@76.126,24.798 cw(c76.97,24.025) 76.97,25.17 ; JP1.2@76.126,25.542 ccw(c76.97,26.315) 76.97,25.17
